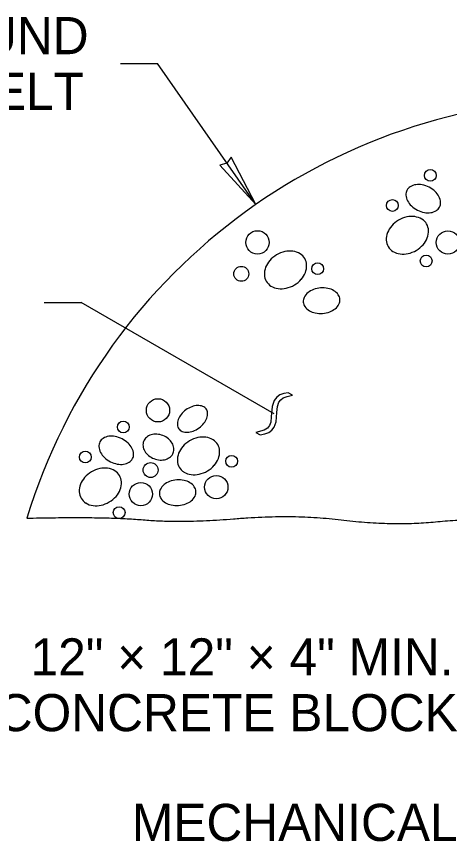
# Model space of a CAD drawing. Extents: x 99862 to 103151, y 100000 to 102076.
# Drawn here: x 100084.4 to 100270.9, y 100201.4 to 100556.8 of the extents above; entities that cross this region are included whole.
import ezdxf

# ---------------------------------------------------------------- set-up
doc = ezdxf.new("R2010")
doc.units = 0
for name, color, linetype in [('Level 1', 7, 'Continuous'), ('Level 10', 7, 'Continuous'), ('Level 15', 7, 'Continuous'), ('Level 20', 7, 'Continuous')]:
    doc.layers.add(name, color=color, linetype=linetype)

msp = doc.modelspace()

# ---------------------------------------------------------------- linework, layer by layer
at = {"layer": 'Level 1'}
msp.add_arc((100333.43, 100265.78), 255.78, 89.0316, 162.9691, dxfattribs=at)
msp.add_open_spline([(100088.82, 100340.7), (100121.57, 100341.52), (100155.86, 100338.56), (100203.47, 100342.57), (100246.83, 100337.27), (100285.41, 100341.25), (100319.94, 100339.65)], degree=2, dxfattribs=at)
at = {"layer": 'Level 10'}
for centre, radius in [((100262.65, 100488.4), 2.54), ((100246.3, 100475.44), 2.54), ((100188.22, 100459.53), 5.02), ((100270.22, 100459.49), 5.02), ((100214.13, 100448.17), 2.54), ((100260.85, 100451.52), 2.54), ((100181.24, 100445.98), 3.22), ((100145.36, 100387.18), 5.02), ((100130.41, 100380), 2.54), ((100114.07, 100367.05), 2.54), ((100177.05, 100365.25), 2.54), ((100142.17, 100361.46), 3.22), ((100170.48, 100354.09), 5.02), ((100137.99, 100351.1), 5.02), ((100128.62, 100343.13), 2.54)]:
    msp.add_circle(centre, radius, dxfattribs=at)
for centre, radius, start, end in [((100256.06, 100480.17), 3.92, 122.2142, 152.8888), ((100257.24, 100478.3), 6.14, 97.8162, 122.2142), ((100257.54, 100476.13), 8.32, 79.0215, 97.8162), ((100256.98, 100473.24), 11.27, 62.8888, 79.0215), ((100256.98, 100473.24), 11.27, 46.756, 62.8888), ((100256.06, 100480.17), 3.92, 152.8888, 183.5633), ((100258.27, 100480.31), 6.14, 183.5633, 207.9613), ((100258.99, 100475.38), 8.32, 27.9613, 46.756), ((100260.92, 100476.41), 6.14, 3.5633, 27.9613), ((100260.2, 100481.34), 8.32, 207.9613, 226.756), ((100263.14, 100476.55), 3.92, 332.8888, 3.5633), ((100262.22, 100483.48), 11.27, 226.756, 242.8888), ((100262.22, 100483.48), 11.27, 242.8888, 259.0215), ((100261.66, 100480.59), 8.32, 259.0215, 277.8162), ((100261.96, 100478.43), 6.14, 277.8162, 302.2142), ((100263.14, 100476.55), 3.92, 302.2142, 332.8888), ((100255.15, 100458.57), 12.2, 120.5557, 138.564), ((100255.15, 100458.57), 12.2, 102.5474, 120.5557), ((100254.63, 100460.91), 9.8, 82.4304, 102.5474), ((100254.87, 100462.74), 7.95, 58.3801, 82.4304), ((100255.91, 100464.43), 5.97, 30.5557, 58.3801), ((100253.35, 100460.16), 9.8, 138.564, 158.681), ((100255.91, 100464.43), 5.97, 2.7312, 30.5557), ((100251.63, 100460.83), 7.95, 158.681, 182.7312), ((100252.21, 100465.01), 9.8, 318.564, 338.681), ((100253.93, 100464.34), 7.95, 338.681, 2.7312), ((100249.65, 100460.73), 5.97, 182.7312, 210.5557), ((100250.41, 100466.6), 12.2, 300.5557, 318.564), ((100202.65, 100443.66), 12.2, 102.5474, 120.5557), ((100202.12, 100446), 9.8, 82.4304, 102.5474), ((100202.37, 100447.83), 7.95, 58.3801, 82.4304), ((100203.41, 100449.52), 5.97, 30.5557, 58.3801), ((100249.65, 100460.73), 5.97, 210.5557, 238.3801), ((100250.69, 100462.42), 7.95, 238.3801, 262.4304), ((100250.93, 100464.25), 9.8, 262.4304, 282.5474), ((100250.41, 100466.6), 12.2, 282.5474, 300.5557), ((100200.84, 100445.25), 9.8, 138.564, 158.681), ((100202.65, 100443.66), 12.2, 120.5557, 138.564), ((100203.41, 100449.52), 5.97, 2.7312, 30.5557), ((100199.12, 100445.92), 7.95, 158.681, 182.7312), ((100201.43, 100449.43), 7.95, 338.681, 2.7312), ((100197.15, 100445.82), 5.97, 182.7312, 210.5557), ((100197.91, 100451.69), 12.2, 300.5557, 318.564), ((100199.71, 100450.1), 9.8, 318.564, 338.681), ((100197.15, 100445.82), 5.97, 210.5557, 238.3801), ((100198.18, 100447.51), 7.95, 238.3801, 262.4304), ((100197.91, 100451.69), 12.2, 282.5474, 300.5557), ((100198.43, 100449.34), 9.8, 262.4304, 282.5474), ((100213.85, 100433.13), 6.14, 129.2706, 153.6686), ((100215.23, 100431.44), 8.32, 110.4759, 129.2706), ((100216.26, 100428.68), 11.27, 94.3432, 110.4759), ((100216.26, 100428.68), 11.27, 78.2105, 94.3432), ((100216.86, 100431.56), 8.32, 59.4158, 78.2104), ((100217.97, 100433.44), 6.14, 35.0177, 59.4158), ((100219.79, 100434.72), 3.92, 4.3432, 35.0177), ((100211.86, 100434.12), 3.92, 153.6687, 184.3432), ((100211.86, 100434.12), 3.92, 184.3432, 215.0177), ((100217.8, 100435.7), 6.14, 309.2706, 333.6686), ((100219.79, 100434.72), 3.92, 333.6687, 4.3432), ((100213.67, 100435.39), 6.14, 215.0177, 239.4158), ((100214.79, 100437.27), 8.32, 239.4158, 258.2104), ((100215.39, 100440.16), 11.27, 274.3432, 290.4759), ((100216.42, 100437.4), 8.32, 290.4759, 309.2706), ((100215.39, 100440.16), 11.27, 258.2105, 274.3432), ((100163.88, 100378.45), 11.02, 126.0848, 141.3252), ((100163.88, 100378.45), 11.02, 110.8443, 126.0848), ((100162.75, 100381.42), 7.84, 92.7495, 110.8443), ((100162.64, 100383.75), 5.51, 68.2848, 92.7495), ((100163.49, 100385.88), 3.22, 36.0848, 68.2848), ((100163.49, 100385.88), 3.22, 3.8847, 36.0848), ((100159.22, 100381.26), 5.51, 159.42, 183.8847), ((100161.4, 100380.44), 7.84, 141.3252, 159.42), ((100159.02, 100386.54), 7.84, 321.3252, 339.42), ((100161.2, 100385.72), 5.51, 339.42, 3.8847), ((100156.93, 100381.1), 3.22, 183.8847, 216.0848), ((100156.54, 100388.53), 11.02, 290.8443, 306.0848), ((100156.54, 100388.53), 11.02, 306.0848, 321.3252), ((100125.3, 100367.74), 8.32, 79.0215, 97.8162), ((100144.04, 100371.2), 5.65, 106.6212, 130.6962), ((100144.42, 100369.91), 6.99, 86.5705, 106.6212), ((100144.32, 100368.16), 8.75, 68.6634, 86.5705), ((100144.32, 100368.16), 8.75, 50.7562, 68.6634), ((100156.93, 100381.1), 3.22, 216.0848, 248.2848), ((100157.78, 100383.23), 5.51, 248.2848, 272.7495), ((100157.67, 100385.55), 7.84, 272.7495, 290.8443), ((100123.82, 100371.78), 3.92, 152.8888, 183.5633), ((100123.82, 100371.78), 3.92, 122.2142, 152.8888), ((100125.01, 100369.9), 6.14, 97.8162, 122.2142), ((100124.74, 100364.84), 11.27, 62.8888, 79.0215), ((100124.74, 100364.84), 11.27, 46.756, 62.8888), ((100126.76, 100366.99), 8.32, 27.9613, 46.756), ((100143.1, 100372.29), 4.21, 158.6634, 186.6305), ((100143.1, 100372.29), 4.21, 130.6962, 158.6634), ((100145.43, 100369.52), 6.99, 30.7055, 50.7562), ((100146.59, 100370.2), 5.65, 6.6305, 30.7055), ((100165.17, 100363.53), 12.2, 120.5557, 138.564), ((100165.17, 100363.53), 12.2, 102.5474, 120.5557), ((100164.65, 100365.87), 9.8, 82.4304, 102.5474), ((100164.89, 100367.7), 7.95, 58.3801, 82.4304), ((100165.93, 100369.39), 5.97, 30.5557, 58.3801), ((100126.04, 100371.92), 6.14, 183.5633, 207.9613), ((100127.97, 100372.94), 8.32, 207.9613, 226.756), ((100128.69, 100368.02), 6.14, 3.5633, 27.9613), ((100144.53, 100372.46), 5.65, 186.6305, 210.7055), ((100145.69, 100373.15), 6.99, 210.7055, 230.7562), ((100148.02, 100370.37), 4.21, 338.6634, 6.6305), ((100163.37, 100365.12), 9.8, 138.564, 158.681), ((100165.93, 100369.39), 5.97, 2.7312, 30.5557), ((100163.95, 100369.3), 7.95, 338.681, 2.7312), ((100129.99, 100375.09), 11.27, 226.756, 242.8888), ((100130.91, 100368.15), 3.92, 302.2142, 332.8888), ((100130.91, 100368.15), 3.92, 332.8888, 3.5633), ((100146.8, 100374.51), 8.75, 230.7562, 248.6634), ((100146.8, 100374.51), 8.75, 248.6634, 266.5705), ((100146.7, 100372.75), 6.99, 266.5705, 286.6212), ((100147.08, 100371.46), 5.65, 286.6212, 310.6962), ((100148.02, 100370.37), 4.21, 310.6962, 338.6634), ((100161.65, 100365.79), 7.95, 158.681, 182.7312), ((100159.67, 100365.7), 5.97, 182.7312, 210.5557), ((100162.23, 100369.97), 9.8, 318.564, 338.681), ((100122.91, 100350.17), 12.2, 102.5474, 120.5557), ((100122.39, 100352.52), 9.8, 82.4304, 102.5474), ((100122.64, 100354.35), 7.95, 58.3801, 82.4304), ((100129.99, 100375.09), 11.27, 242.8888, 259.0215), ((100129.43, 100372.2), 8.32, 259.0215, 277.8162), ((100129.72, 100370.03), 6.14, 277.8162, 302.2142), ((100159.67, 100365.7), 5.97, 210.5557, 238.3801), ((100160.43, 100371.56), 12.2, 300.5557, 318.564), ((100121.11, 100351.76), 9.8, 138.564, 158.681), ((100122.91, 100350.17), 12.2, 120.5557, 138.564), ((100123.67, 100356.04), 5.97, 30.5557, 58.3801), ((100123.67, 100356.04), 5.97, 2.7312, 30.5557), ((100160.71, 100367.38), 7.95, 238.3801, 262.4304), ((100160.95, 100369.21), 9.8, 262.4304, 282.5474), ((100160.43, 100371.56), 12.2, 282.5474, 300.5557), ((100119.39, 100352.44), 7.95, 158.681, 182.7312), ((100121.7, 100355.94), 7.95, 338.681, 2.7312), ((100151.85, 100350.41), 6.14, 129.2706, 153.6686), ((100153.24, 100348.72), 8.32, 110.4759, 129.2706), ((100154.27, 100345.96), 11.27, 94.3432, 110.4759), ((100154.27, 100345.96), 11.27, 78.2105, 94.3432), ((100154.87, 100348.84), 8.32, 59.4158, 78.2104), ((100155.98, 100350.72), 6.14, 35.0177, 59.4158), ((100117.41, 100352.34), 5.97, 182.7312, 210.5557), ((100119.98, 100356.61), 9.8, 318.564, 338.681), ((100149.86, 100351.4), 3.92, 153.6687, 184.3432), ((100157.8, 100352), 3.92, 4.3432, 35.0177), ((100157.8, 100352), 3.92, 333.6687, 4.3432), ((100117.41, 100352.34), 5.97, 210.5557, 238.3801), ((100118.17, 100358.2), 12.2, 282.5474, 300.5557), ((100118.17, 100358.2), 12.2, 300.5557, 318.564), ((100149.86, 100351.4), 3.92, 184.3432, 215.0177), ((100151.68, 100352.67), 6.14, 215.0177, 239.4158), ((100154.43, 100354.67), 8.32, 290.4759, 309.2706), ((100155.81, 100352.98), 6.14, 309.2706, 333.6686), ((100118.45, 100354.03), 7.95, 238.3801, 262.4304), ((100118.7, 100355.86), 9.8, 262.4304, 282.5474), ((100152.79, 100354.55), 8.32, 239.4158, 258.2104), ((100153.4, 100357.44), 11.27, 258.2105, 274.3432), ((100153.4, 100357.44), 11.27, 274.3432, 290.4759)]:
    msp.add_arc(centre, radius, start, end, dxfattribs=at)
at = {"layer": 'Level 15'}
for p, q in [((100129.17, 100536.61), (100145.17, 100536.61)), ((100187.44, 100475.8), (100145.17, 100536.61)), ((100096.27, 100433.62), (100112.27, 100433.62)), ((100195.37, 100385.65), (100112.27, 100433.62))]:
    msp.add_line(p, q, dxfattribs=at)
msp.add_lwpolyline([(100187.44, 100475.8), (100176.86, 100496.25), (100175.01, 100493.68), (100171.96, 100492.84)], close=True, dxfattribs=at)
at = {"layer": 'Level 20'}
for p, q in [((100197.84, 100393.82), (100196.47, 100392.8)), ((100199.52, 100394.45), (100197.84, 100393.82)), ((100201.49, 100394.71), (100199.52, 100394.45)), ((100203.32, 100393.65), (100201.49, 100394.71)), ((100195.4, 100391.41), (100194.47, 100388.85)), ((100196.47, 100392.8), (100195.4, 100391.41)), ((100196.78, 100388.85), (100197.41, 100390.66)), ((100197.41, 100390.66), (100198.23, 100391.71)), ((100198.23, 100391.71), (100199.33, 100392.51)), ((100199.33, 100392.51), (100200.95, 100393.14)), ((100200.95, 100393.14), (100203.32, 100393.65)), ((100194.47, 100388.85), (100194.1, 100384.45)), ((100196.55, 100386.31), (100196.78, 100388.85)), ((100194.1, 100384.45), (100193.9, 100382.04)), ((100196.29, 100382.22), (100196.55, 100386.31)), ((100193.37, 100380.63), (100192.45, 100379.55)), ((100193.9, 100382.04), (100193.37, 100380.63)), ((100194.39, 100378.6), (100195.4, 100379.93)), ((100195.4, 100379.93), (100196.29, 100382.22)), ((100191.05, 100378.68), (100187.49, 100377.69)), ((100187.49, 100377.69), (100189.32, 100376.64)), ((100189.32, 100376.64), (100191.43, 100377)), ((100192.45, 100379.55), (100191.05, 100378.68)), ((100191.43, 100377), (100193.09, 100377.64)), ((100193.09, 100377.64), (100194.39, 100378.6))]:
    msp.add_line(p, q, dxfattribs=at)

# ---------------------------------------------------------------- texts
for s, p in [('15 POUND', (100008.48, 100540.61)), ('ASPHALTIC FELT', (99936.33, 100516.61)), ('12" × 12" × 4" MIN.', (100090.46, 100272.95)), ('CONCRETE BLOCK', (100075.92, 100248.95))]:
    msp.add_text(s, height=16, dxfattribs=at).set_placement(p)
msp.add_text('MECHANICAL JOINT', height=16, rotation=360, dxfattribs=at).set_placement((100134.13, 100201.66))

doc.saveas('drawing.dxf')
